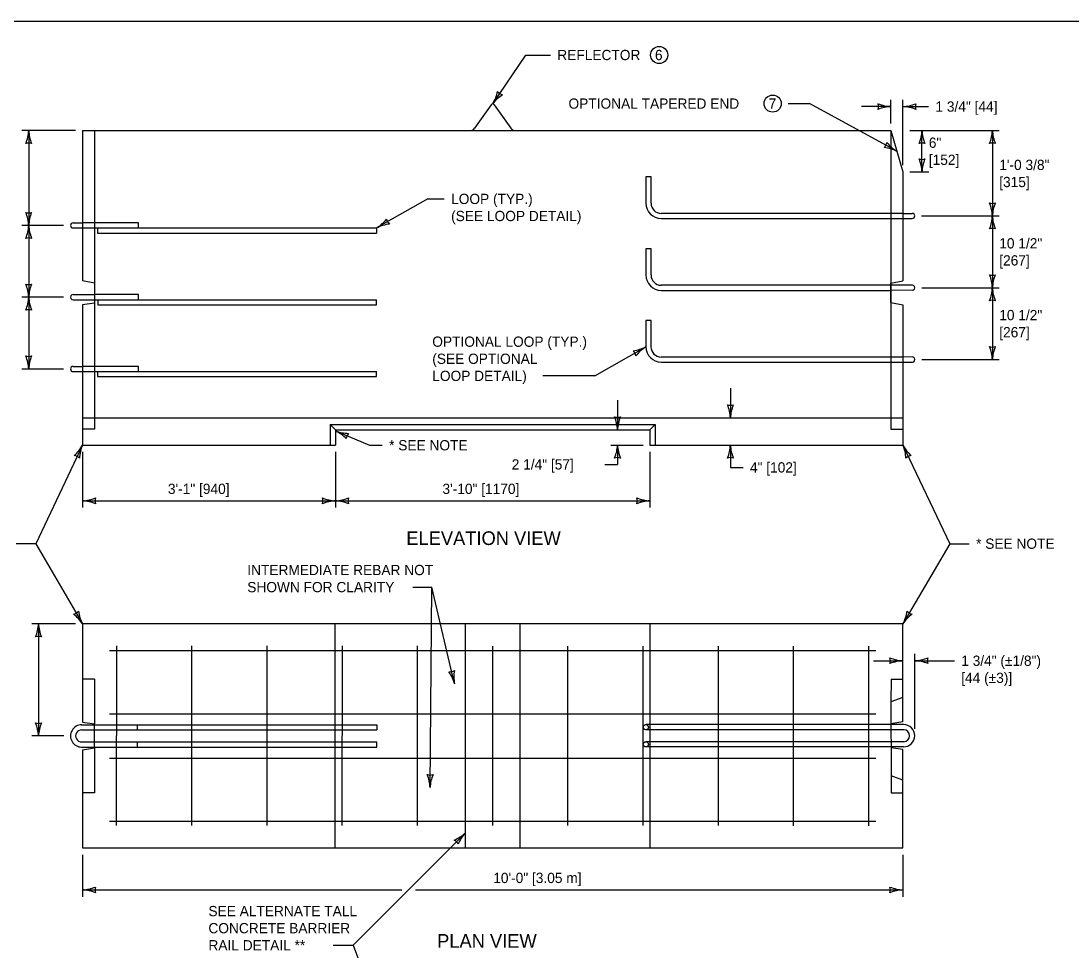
# Model space of a CAD drawing. Extents: x 49991.4 to 50021, y 49987.6 to 50011.4.
# Drawn here: x 50002.72 to 50008.86, y 49993.56 to 49999 of the extents above; entities that cross this region are included whole.
import ezdxf

# ---------------------------------------------------------------- set-up
doc = ezdxf.new("R2010")
doc.units = 0
for name, color, linetype in [('Level 1', 7, 'Continuous'), ('Level 2', 7, 'Continuous'), ('Level 3', 7, 'Continuous'), ('Level 4', 7, 'Continuous')]:
    doc.layers.add(name, color=color, linetype=linetype)

msp = doc.modelspace()

# ---------------------------------------------------------------- linework, layer by layer
at = {"layer": 'Level 1'}
for p, q in [((50003.0765, 49998.3587), (50007.8065, 49998.3587)), ((50003.0765, 49998.3587), (50003.0765, 49997.4789)), ((50007.8065, 49998.3587), (50007.8765, 49998.1161)), ((50007.8765, 49998.1161), (50007.8765, 49997.4792)), ((50007.8765, 49997.8737), (50007.931, 49997.8737)), ((50003.0215, 49997.8187), (50003.0766, 49997.8185)), ((50007.8765, 49997.8437), (50007.9311, 49997.8439)), ((50003.0215, 49997.7886), (50003.0765, 49997.7886)), ((50003.1468, 49997.4652), (50003.0765, 49997.4789)), ((50003.1468, 49997.4652), (50003.1468, 49997.3494)), ((50007.8065, 49997.4654), (50007.8765, 49997.4792)), ((50007.8065, 49997.3532), (50007.8065, 49997.4654)), ((50007.9315, 49997.4539), (50007.8065, 49997.4537)), ((50003.0215, 49997.3986), (50003.1468, 49997.3987)), ((50007.9315, 49997.4238), (50007.8065, 49997.4237)), ((50003.0215, 49997.3687), (50003.1468, 49997.3688)), ((50003.1468, 49997.3494), (50003.0766, 49997.3389)), ((50003.0766, 49997.3389), (50003.0766, 49996.5187)), ((50007.8065, 49997.3532), (50007.8765, 49997.3392)), ((50007.8765, 49997.3392), (50007.8765, 49996.5187)), ((50007.9317, 49997.0338), (50007.8765, 49997.0336)), ((50003.0215, 49996.9787), (50003.0766, 49996.9789)), ((50007.8765, 49997.0036), (50007.9316, 49997.0037)), ((50003.0215, 49996.9487), (50003.0766, 49996.949)), ((50004.5264, 49996.6386), (50004.5565, 49996.6086)), ((50004.5264, 49996.6386), (50006.4265, 49996.6386)), ((50004.5264, 49996.6386), (50004.5264, 49996.5187)), ((50004.5565, 49996.6086), (50004.5565, 49996.5187)), ((50004.5565, 49996.6086), (50006.3964, 49996.6086)), ((50006.4265, 49996.6386), (50006.3964, 49996.6086)), ((50006.3964, 49996.6086), (50006.3964, 49996.5187)), ((50006.4265, 49996.6386), (50006.4265, 49996.5187)), ((50003.0766, 49996.5187), (50004.5565, 49996.5187)), ((50006.3964, 49996.5187), (50007.8765, 49996.5187)), ((50007.8766, 49995.4723), (50003.0766, 49995.4723)), ((50003.0766, 49995.4723), (50003.0766, 49994.898)), ((50005.3166, 49994.1623), (50005.3166, 49995.4723)), ((50005.6366, 49994.1623), (50005.6366, 49995.4723)), ((50007.8766, 49994.8989), (50007.8766, 49995.4723)), ((50003.2341, 49995.3166), (50007.7186, 49995.3166)), ((50003.2766, 49994.2932), (50003.2768, 49995.3438)), ((50003.7166, 49994.2931), (50003.7168, 49995.3437)), ((50004.1566, 49994.293), (50004.1568, 49995.3436)), ((50004.5966, 49994.2929), (50004.5968, 49995.3435)), ((50005.0366, 49994.2928), (50005.0368, 49995.3434)), ((50005.4766, 49994.2927), (50005.4768, 49995.3433)), ((50005.9166, 49994.2926), (50005.9168, 49995.3432)), ((50006.3566, 49994.2925), (50006.3568, 49995.343)), ((50006.7966, 49994.2924), (50006.7968, 49995.3429)), ((50007.2366, 49994.2923), (50007.2368, 49995.3428)), ((50007.6766, 49994.2922), (50007.6768, 49995.3427)), ((50007.8766, 49995.0416), (50007.8063, 49995.0166)), ((50007.8063, 49995.0166), (50007.8067, 49994.583)), ((50003.2341, 49994.9473), (50007.7186, 49994.9473)), ((50003.0714, 49994.8827), (50003.1469, 49994.8824)), ((50003.0766, 49994.898), (50003.1469, 49994.8872)), ((50003.1469, 49994.7474), (50003.1469, 49994.8872)), ((50007.8766, 49994.8989), (50007.8064, 49994.888)), ((50007.8808, 49994.8836), (50007.8064, 49994.8834)), ((50003.0714, 49994.8524), (50003.1469, 49994.8524)), ((50007.8808, 49994.8534), (50007.8064, 49994.8533)), ((50003.0714, 49994.7824), (50003.1469, 49994.7822)), ((50003.0714, 49994.7522), (50003.1469, 49994.7521)), ((50003.0766, 49994.7363), (50003.1469, 49994.7474)), ((50007.8808, 49994.7834), (50007.8065, 49994.7831)), ((50007.8808, 49994.7531), (50007.8066, 49994.753)), ((50007.8766, 49994.7372), (50007.8066, 49994.7483)), ((50003.0766, 49994.7363), (50003.0766, 49994.1623)), ((50003.2341, 49994.688), (50007.7186, 49994.688)), ((50007.8766, 49994.1623), (50007.8766, 49994.7372)), ((50007.8766, 49994.558), (50007.8067, 49994.583)), ((50003.2341, 49994.3179), (50007.7186, 49994.3179)), ((50003.0766, 49994.1623), (50007.8766, 49994.1623))]:
    msp.add_line(p, q, dxfattribs=at)
msp.add_lwpolyline([(49999.3835, 49998.9992), (50016.7501, 49998.9992), (50016.7501, 49987.7988), (49999.3835, 49987.7988)], close=True, dxfattribs=at)
for centre, radius, start, end in [((50007.931, 49997.8588), 0.0149, 270.58084, 89.93308), ((50003.0215, 49997.8037), 0.015, 90.00376, 269.98914), ((50007.9315, 49997.4388), 0.015, 269.99727, 90.00272), ((50003.0212, 49997.3837), 0.015, 88.80732, 271.23347), ((50007.9319, 49997.0188), 0.015, 268.79877, 90.74505), ((50003.0215, 49996.9637), 0.015, 90.04087, 269.95913)]:
    msp.add_arc(centre, radius, start, end, dxfattribs=at)
for centre, major_axis, start_param, end_param in [((50003.0714, 49994.8174), (0, 0.0652), 0, 3.141593), ((50007.8808, 49994.8184), (0, 0.0652), 3.141593, 6.283185), ((50003.0714, 49994.8174), (0, 0.035), 0, 3.141593), ((50007.8808, 49994.8184), (0, 0.035), 3.141593, 6.283185)]:
    msp.add_ellipse(centre, major_axis=major_axis, ratio=0.991158, start_param=start_param, end_param=end_param, dxfattribs=at)
at = {"layer": 'Level 2'}
for centre in [(50006.4502, 49998.8003), (50007.1145, 49998.5161)]:
    msp.add_circle(centre, 0.05, dxfattribs=at)
at = {"layer": 'Level 3'}
for p, q in [((50005.4765, 49998.5143), (50005.6707, 49998.8003)), ((50005.6707, 49998.8003), (50005.8145, 49998.8003)), ((50005.4683, 49998.5095), (50005.3703, 49998.3715)), ((50005.4847, 49998.5095), (50005.5826, 49998.3715)), ((50007.2045, 49998.5161), (50007.3289, 49998.5161)), ((50007.8416, 49998.2373), (50007.3289, 49998.5161)), ((50007.8065, 49998.4987), (50007.6331, 49998.4987)), ((50007.8065, 49998.3987), (50007.8065, 49998.5387)), ((50007.8765, 49998.1561), (50007.8765, 49998.5387)), ((50007.8765, 49998.4987), (50008.0264, 49998.4987)), ((50003.0365, 49998.3587), (50002.7221, 49998.3587)), ((50002.7621, 49998.3587), (50002.7621, 49997.8036)), ((50007.9165, 49998.3587), (50008.4398, 49998.3587)), ((50007.9878, 49998.1161), (50007.9878, 49998.3587)), ((50008.3998, 49998.3587), (50008.3998, 49997.8588)), ((50007.9165, 49998.1161), (50008.0278, 49998.1161)), ((50005.0967, 49997.9586), (50004.7975, 49997.7886)), ((50005.0967, 49997.9586), (50005.1932, 49997.9586)), ((50007.9859, 49997.8588), (50008.4398, 49997.8588)), ((50008.3998, 49997.8588), (50008.3998, 49997.4388)), ((50002.9665, 49997.8036), (50002.7222, 49997.8036)), ((50002.7621, 49997.8036), (50002.7622, 49997.3836)), ((50002.9663, 49997.3836), (50002.7222, 49997.3836)), ((50002.7622, 49997.3836), (50002.7622, 49996.9636)), ((50007.9866, 49997.4388), (50008.4398, 49997.4388)), ((50008.3998, 49997.4388), (50008.3998, 49997.0188)), ((50006.0734, 49996.9235), (50006.3725, 49997.0935)), ((50007.9869, 49997.0188), (50008.4398, 49997.0188)), ((50002.9665, 49996.9636), (50002.7222, 49996.9636)), ((50006.0734, 49996.9235), (50005.7705, 49996.9235)), ((50006.867, 49996.8522), (50006.867, 49996.6787)), ((50006.2067, 49996.782), (50006.2067, 49996.6086)), ((50004.5565, 49996.6011), (50004.7561, 49996.5176)), ((50003.0766, 49996.5187), (50002.8033, 49995.9416)), ((50003.0766, 49996.4787), (50003.0766, 49996.1526)), ((50004.5565, 49996.4787), (50004.5565, 49996.1526)), ((50004.7561, 49996.5176), (50004.8305, 49996.5176)), ((50006.1667, 49996.5187), (50006.3564, 49996.5187)), ((50006.2067, 49996.5187), (50006.2067, 49996.4055)), ((50006.3964, 49996.4787), (50006.3964, 49996.1526)), ((50006.867, 49996.5187), (50006.867, 49996.3881)), ((50007.8765, 49996.5187), (50008.1499, 49995.9418)), ((50006.1324, 49996.4055), (50006.2067, 49996.4055)), ((50006.867, 49996.3881), (50006.9414, 49996.3881)), ((50003.0766, 49996.1926), (50004.5565, 49996.1926)), ((50004.5565, 49996.1926), (50006.3964, 49996.1926)), ((50002.8033, 49995.9416), (50002.6888, 49995.9416)), ((50002.8033, 49995.9416), (50003.0766, 49995.4723)), ((50008.1499, 49995.9418), (50007.8766, 49995.4723)), ((50008.1499, 49995.9418), (50008.2644, 49995.9418)), ((50005.0083, 49995.6878), (50005.1197, 49995.6878)), ((50005.1098, 49994.5151), (50005.1197, 49995.6878)), ((50005.2532, 49995.1226), (50005.1197, 49995.6878)), ((50003.0366, 49995.4723), (50002.7795, 49995.4723)), ((50002.8195, 49995.4723), (50002.8195, 49994.8174)), ((50007.9452, 49994.8584), (50007.9452, 49995.2972)), ((50007.7032, 49995.2572), (50007.8766, 49995.2572)), ((50007.9452, 49995.2572), (50008.1774, 49995.2572)), ((50002.9667, 49994.8174), (50002.7795, 49994.8174)), ((50004.6608, 49993.5928), (50005.3166, 49994.2502)), ((50003.0765, 49994.1223), (50003.0765, 49993.8767)), ((50007.8765, 49994.1223), (50007.8765, 49993.8767)), ((50003.0765, 49993.9167), (50004.9439, 49993.9167)), ((50005.0239, 49993.9167), (50007.8765, 49993.9167)), ((50004.5422, 49993.5928), (50004.6608, 49993.5928)), ((50004.6608, 49993.5928), (50005.3799, 49991.6271))]:
    msp.add_line(p, q, dxfattribs=at)
for centre, radius, start, end in [((50005.2775, 49998.6355), 0.233, 328.64825, 347.8981), ((50005.6551, 49998.3819), 0.2223, 123.27695, 143.46046), ((50005.5485, 49998.6203), 0.0548, 217.95976, 253.68212), ((50005.4765, 49998.5037), 0.0101, 35.34894, 144.65106), ((50007.8157, 49998.7208), 0.2223, 247.45601, 267.63952), ((50007.6783, 49998.4987), 0.0548, 342.13882, 17.86118), ((50007.818, 49998.266), 0.233, 92.82731, 112.07716), ((50007.865, 49998.7314), 0.233, 272.82731, 292.07716), ((50007.8673, 49998.2766), 0.2223, 67.45601, 87.63952), ((50008.0047, 49998.4987), 0.0548, 162.13882, 197.86118), ((50005.3456, 49998.389), 0.0303, 270, 324.65106), ((50005.6073, 49998.389), 0.0303, 215.34894, 270), ((50002.54, 49998.3679), 0.2223, 337.45803, 357.64153), ((50002.9948, 49998.3702), 0.233, 182.82933, 202.07918), ((50007.7657, 49998.3679), 0.2223, 337.45601, 357.63952), ((50008.2206, 49998.3702), 0.233, 182.82731, 202.07716), ((50008.1776, 49998.3679), 0.2223, 337.45759, 357.6411), ((50008.6325, 49998.3702), 0.233, 182.82889, 202.07874), ((50002.7621, 49998.2305), 0.0548, 72.14083, 107.86319), ((50007.7289, 49998.2985), 0.0548, 313.60126, 349.32362), ((50007.7405, 49998.0273), 0.233, 64.28976, 83.53961), ((50007.9557, 49998.428), 0.2223, 218.91846, 239.10196), ((50007.9878, 49998.2305), 0.0548, 72.13882, 107.86118), ((50008.3998, 49998.2305), 0.0548, 72.1404, 107.86276), ((50007.9878, 49998.2444), 0.0548, 252.13882, 287.86118), ((50007.7551, 49998.1047), 0.233, 2.82731, 22.07716), ((50008.21, 49998.107), 0.2223, 157.45601, 177.63952), ((50008.3998, 49997.987), 0.0548, 252.1404, 287.86276), ((50008.1671, 49997.8473), 0.233, 2.82889, 22.07874), ((50008.6219, 49997.8497), 0.2223, 157.45759, 177.6411), ((50002.7621, 49997.9319), 0.0548, 252.14083, 287.86319), ((50002.5294, 49997.7921), 0.233, 2.82932, 22.07917), ((50002.9843, 49997.7945), 0.2223, 157.45802, 177.64153), ((50004.6798, 49997.9772), 0.2223, 301.96607, 322.14958), ((50004.909, 49997.8519), 0.0548, 191.74441, 227.46677), ((50008.1777, 49997.868), 0.2223, 337.45759, 357.6411), ((50008.6325, 49997.8703), 0.233, 182.82889, 202.07874), ((50002.54, 49997.8128), 0.2223, 337.45803, 357.64153), ((50002.9949, 49997.8151), 0.233, 182.82933, 202.07918), ((50004.9025, 49997.5806), 0.233, 97.52843, 116.77828), ((50008.3998, 49997.7306), 0.0548, 72.1404, 107.86276), ((50002.7622, 49997.6754), 0.0548, 72.14083, 107.86319), ((50008.3998, 49997.567), 0.0548, 252.1404, 287.86276), ((50008.1671, 49997.4273), 0.233, 2.82889, 22.07874), ((50008.6219, 49997.4297), 0.2223, 157.45759, 177.6411), ((50002.7622, 49997.5119), 0.0548, 252.14083, 287.86319), ((50002.5294, 49997.3721), 0.233, 2.82932, 22.07917), ((50002.9843, 49997.3745), 0.2223, 157.45802, 177.64153), ((50002.54, 49997.3928), 0.2223, 337.45803, 357.64153), ((50002.9949, 49997.3951), 0.233, 182.82933, 202.07918), ((50008.1777, 49997.448), 0.2223, 337.45759, 357.6411), ((50008.6325, 49997.4503), 0.233, 182.82889, 202.07874), ((50008.3998, 49997.3106), 0.0548, 72.1404, 107.86276), ((50002.7622, 49997.2554), 0.0548, 72.14083, 107.86319), ((50006.2676, 49997.3015), 0.233, 277.52842, 296.77828), ((50006.4902, 49996.9049), 0.2223, 121.96607, 142.14957), ((50008.3998, 49997.147), 0.0548, 252.1404, 287.86276), ((50008.1671, 49997.0073), 0.233, 2.82889, 22.07874), ((50008.622, 49997.0097), 0.2223, 157.45759, 177.6411), ((50002.7622, 49997.0919), 0.0548, 252.14083, 287.86319), ((50002.5295, 49996.9521), 0.233, 2.82932, 22.07917), ((50002.9843, 49996.9545), 0.2223, 157.45802, 177.64153), ((50006.2611, 49997.0301), 0.0548, 11.74441, 47.46677), ((50006.867, 49996.8069), 0.0548, 252.13882, 287.86118), ((50006.6343, 49996.6672), 0.233, 2.82731, 22.07716), ((50007.0892, 49996.6696), 0.2223, 157.45601, 177.63952), ((50006.2067, 49996.7368), 0.0548, 252.13882, 287.86118), ((50005.974, 49996.5971), 0.233, 2.82731, 22.07716), ((50006.4289, 49996.5994), 0.2223, 157.45601, 177.63952), ((50004.4622, 49996.3998), 0.2223, 44.73985, 64.92336), ((50004.6357, 49996.8202), 0.233, 250.11115, 269.361), ((50004.6747, 49996.5516), 0.0548, 139.42266, 175.14502), ((50002.8797, 49996.622), 0.2223, 312.11968, 332.30319), ((50003.2918, 49996.4295), 0.233, 157.49098, 176.74083), ((50005.9846, 49996.5279), 0.2223, 337.45601, 357.63952), ((50006.4395, 49996.5302), 0.233, 182.82731, 202.07716), ((50006.6449, 49996.5279), 0.2223, 337.45601, 357.63952), ((50007.0998, 49996.5302), 0.233, 182.82731, 202.07716), ((50007.6718, 49996.4319), 0.2223, 2.80835, 22.99186), ((50008.0819, 49996.6287), 0.233, 208.17965, 227.4295), ((50003.0217, 49996.4028), 0.0548, 46.80249, 82.52485), ((50006.2067, 49996.3905), 0.0548, 72.13882, 107.86118), ((50006.867, 49996.3905), 0.0548, 72.13882, 107.86118), ((50007.9314, 49996.4028), 0.0548, 97.49116, 133.21352), ((50003.0651, 49996.4253), 0.233, 272.82731, 292.07716), ((50003.0674, 49995.9705), 0.2223, 67.45601, 87.63952), ((50003.2048, 49996.1926), 0.0548, 162.13882, 197.86118), ((50004.5656, 49996.4147), 0.2223, 247.45601, 267.63952), ((50004.4282, 49996.1926), 0.0548, 342.13882, 17.86118), ((50004.568, 49995.9599), 0.233, 92.82731, 112.07716), ((50004.545, 49996.4253), 0.233, 272.82731, 292.07716), ((50004.5473, 49995.9705), 0.2223, 67.45601, 87.63952), ((50004.6847, 49996.1926), 0.0548, 162.13882, 197.86118), ((50006.4056, 49996.4147), 0.2223, 247.45601, 267.63952), ((50006.2682, 49996.1926), 0.0548, 342.13882, 17.86118), ((50006.4079, 49995.9599), 0.233, 92.82731, 112.07716), ((50003.0121, 49995.5831), 0.0548, 282.34946, 318.07182), ((50003.2732, 49995.5762), 0.2223, 187.66665, 207.85016), ((50007.6697, 49995.5794), 0.233, 332.624, 351.87385), ((50007.9411, 49995.5831), 0.0548, 221.93551, 257.65787), ((50002.8813, 49995.3453), 0.233, 33.03795, 52.2878), ((50008.064, 49995.3526), 0.2223, 127.2527, 147.43621), ((50002.5973, 49995.4814), 0.2223, 337.45601, 357.63952), ((50003.0522, 49995.4838), 0.233, 182.82731, 202.07716), ((50002.8195, 49995.3441), 0.0548, 72.13882, 107.86118), ((50007.8858, 49995.4793), 0.2223, 247.45601, 267.63952), ((50007.7484, 49995.2572), 0.0548, 342.13882, 17.86118), ((50007.8881, 49995.0245), 0.233, 92.82731, 112.07716), ((50007.9337, 49995.4899), 0.233, 272.82731, 292.07716), ((50007.936, 49995.035), 0.2223, 67.45601, 87.63952), ((50008.0734, 49995.2572), 0.0548, 162.13882, 197.86118), ((50005.2237, 49995.2474), 0.0548, 265.42436, 301.14672), ((50005.0293, 49995.058), 0.233, 16.11285, 35.3627), ((50005.4715, 49995.1648), 0.2223, 170.74155, 190.92506), ((50002.8195, 49994.9457), 0.0548, 252.13882, 287.86118), ((50002.5867, 49994.8059), 0.233, 2.82731, 22.07716), ((50003.0416, 49994.8083), 0.2223, 157.45601, 177.63952), ((50005.1108, 49994.6433), 0.0548, 251.65224, 287.3746), ((50004.877, 49994.5056), 0.233, 2.34073, 21.59058), ((50005.3318, 49994.5041), 0.2223, 156.96943, 177.15294), ((50005.1658, 49994.4136), 0.2223, 292.52743, 312.71094), ((50005.4894, 49994.094), 0.233, 137.89873, 157.14858), ((50005.226, 49994.1594), 0.0548, 27.21024, 62.9326), ((50003.0651, 49994.1494), 0.233, 272.82731, 292.07716), ((50003.0674, 49993.6946), 0.2223, 67.45601, 87.63952), ((50003.2048, 49993.9167), 0.0548, 162.13882, 197.86118), ((50007.8857, 49994.1388), 0.2223, 247.45601, 267.63952), ((50007.7483, 49993.9167), 0.0548, 342.13882, 17.86118), ((50007.888, 49993.684), 0.233, 92.82731, 112.07716)]:
    msp.add_arc(centre, radius, start, end, dxfattribs=at)
at = {"layer": 'Level 4'}
for p, q in [((50003.1468, 49998.3587), (50003.1468, 49997.4652)), ((50007.8065, 49998.3587), (50007.8065, 49996.6123)), ((50006.4026, 49998.0867), (50006.3726, 49998.0867)), ((50006.3726, 49998.0867), (50006.3726, 49997.9335)), ((50006.4026, 49997.9335), (50006.4026, 49998.0867)), ((50007.8765, 49997.8737), (50006.4625, 49997.8737)), ((50003.4051, 49997.8185), (50003.0766, 49997.8185)), ((50003.4051, 49997.8185), (50003.0766, 49997.8185)), ((50003.4051, 49997.7886), (50003.4051, 49997.8185)), ((50006.4625, 49997.8437), (50007.8765, 49997.8437)), ((50003.0766, 49997.7886), (50004.7975, 49997.7886)), ((50003.1654, 49997.7886), (50003.1654, 49997.7586)), ((50003.1654, 49997.7586), (50004.7975, 49997.7586)), ((50004.7975, 49997.7886), (50004.7975, 49997.7586)), ((50006.4028, 49997.6667), (50006.3727, 49997.6667)), ((50006.3727, 49997.6667), (50006.3727, 49997.5135)), ((50006.4028, 49997.5135), (50006.4028, 49997.6667)), ((50007.8065, 49997.4537), (50006.4626, 49997.4537)), ((50003.4052, 49997.3987), (50003.1468, 49997.3987)), ((50003.4052, 49997.3688), (50003.4052, 49997.3987)), ((50006.4626, 49997.4237), (50007.8065, 49997.4237)), ((50003.1468, 49997.3688), (50004.7976, 49997.3688)), ((50003.1468, 49997.3494), (50003.1468, 49996.6123)), ((50003.1655, 49997.3688), (50003.1655, 49997.3388)), ((50003.1655, 49997.3388), (50004.7976, 49997.3388)), ((50004.7976, 49997.3388), (50004.7976, 49997.3688)), ((50006.4026, 49997.2466), (50006.3725, 49997.2466)), ((50006.3725, 49997.2466), (50006.3725, 49997.0935)), ((50006.4026, 49997.0935), (50006.4026, 49997.2466)), ((50007.8765, 49997.0336), (50006.4624, 49997.0336)), ((50003.4051, 49996.9789), (50003.0766, 49996.9789)), ((50003.4051, 49996.949), (50003.4051, 49996.9789)), ((50006.4624, 49997.0036), (50007.8765, 49997.0036)), ((50003.0766, 49996.949), (50004.7975, 49996.949)), ((50003.1654, 49996.949), (50003.1654, 49996.9191)), ((50003.1654, 49996.9191), (50004.7975, 49996.9191)), ((50004.7975, 49996.9191), (50004.7975, 49996.949)), ((50003.0766, 49996.6787), (50007.8765, 49996.6787)), ((50003.1468, 49996.6123), (50003.0766, 49996.6123)), ((50007.8065, 49996.6123), (50007.8765, 49996.6123)), ((50004.5557, 49994.1623), (50004.5557, 49995.4723)), ((50006.3972, 49994.1623), (50006.3972, 49995.4723)), ((50003.1469, 49995.1501), (50003.0766, 49995.1501)), ((50003.1469, 49995.1501), (50003.1469, 49994.8872)), ((50007.8067, 49995.1501), (50007.8063, 49995.0166)), ((50007.8067, 49995.1501), (50007.8766, 49995.1501)), ((50003.1469, 49994.8824), (50004.7979, 49994.8824)), ((50003.3991, 49994.8524), (50003.3991, 49994.8824)), ((50004.7979, 49994.8824), (50004.7979, 49994.8524)), ((50007.8064, 49994.8834), (50006.3725, 49994.8834)), ((50003.1469, 49994.8524), (50004.7979, 49994.8524)), ((50007.8064, 49994.8533), (50006.3725, 49994.8533)), ((50003.1469, 49994.7822), (50004.7979, 49994.7822)), ((50003.1469, 49994.7521), (50004.7979, 49994.7521)), ((50003.1469, 49994.7474), (50003.1469, 49994.4845)), ((50003.3991, 49994.7521), (50003.3991, 49994.7822)), ((50004.7979, 49994.7521), (50004.7979, 49994.7822)), ((50007.8065, 49994.7831), (50006.3725, 49994.7831)), ((50007.8066, 49994.753), (50006.3725, 49994.753)), ((50007.8067, 49994.583), (50007.8067, 49994.4845)), ((50003.1469, 49994.4845), (50003.0766, 49994.4845)), ((50007.8067, 49994.4845), (50007.8766, 49994.4845)), ((50004.5422, 49993.5928), (50004.5422, 49993.5928))]:
    msp.add_line(p, q, dxfattribs=at)
for centre in [(50006.3725, 49994.8683), (50006.3725, 49994.7681)]:
    msp.add_circle(centre, 0.015, dxfattribs=at)
for centre, radius, start, end in [((50006.4631, 49997.9342), 0.0905, 180.43427, 269.60389), ((50006.4625, 49997.9335), 0.0599, 180, 270), ((50006.4632, 49997.5142), 0.0905, 180.43427, 269.60389), ((50006.4626, 49997.5135), 0.0599, 180, 270), ((50006.4631, 49997.0942), 0.0905, 180.43427, 269.60389), ((50006.4624, 49997.0935), 0.0599, 180, 270)]:
    msp.add_arc(centre, radius, start, end, dxfattribs=at)

# ---------------------------------------------------------------- texts
at = {"layer": 'Level 2'}
for s, height, p in [('REFLECTOR', 0.06, (50005.8545, 49998.7703)), ('6', 0.06, (50006.4257, 49998.7703)), ('OPTIONAL TAPERED END', 0.06, (50005.9199, 49998.4861)), ('7', 0.06, (50007.0907, 49998.4861)), ('1 3/4" [44]', 0.06, (50008.0664, 49998.4687)), ('6"', 0.06, (50008.0278, 49998.2574)), ('[152]', 0.06, (50008.0278, 49998.1574)), ('1\'-0 3/8"', 0.06, (50008.4398, 49998.1275)), ('[315]', 0.06, (50008.4398, 49998.0275)), ('LOOP (TYP.)', 0.06, (50005.2332, 49997.9286)), ('(SEE LOOP DETAIL)', 0.06, (50005.2332, 49997.8286)), ('10 1/2"', 0.06, (50008.4398, 49997.6689)), ('[267]', 0.06, (50008.4398, 49997.5689)), ('10 1/2"', 0.06, (50008.4398, 49997.2489)), ('[267]', 0.06, (50008.4398, 49997.1489)), ('OPTIONAL LOOP (TYP.)', 0.06, (50005.1229, 49997.0935)), ('(SEE OPTIONAL', 0.06, (50005.1229, 49996.9935)), ('LOOP DETAIL)', 0.06, (50005.1229, 49996.8935)), ('* SEE NOTE', 0.06, (50004.8705, 49996.4876)), ('2 1/4" [57]', 0.06, (50005.5878, 49996.3755)), ('4" [102]', 0.06, (50006.9814, 49996.3581)), ('3\'-1" [940]', 0.06, (50003.5764, 49996.2326)), ('3\'-10" [1170]', 0.06, (50005.1825, 49996.2326)), ('ELEVATION VIEW', 0.08, (50004.9711, 49995.9341)), ('* SEE NOTE', 0.06, (50008.3044, 49995.9118)), ('INTERMEDIATE REBAR NOT', 0.06, (50004.0406, 49995.7578)), ('SHOWN FOR CLARITY', 0.06, (50004.0406, 49995.6578)), ('1 3/4" (±1/8")', 0.06, (50008.2174, 49995.2272)), ('[44 (±3)]', 0.06, (50008.2174, 49995.1272)), ('10\'-0" [3.05 m]', 0.06, (50005.4796, 49993.9567)), ('SEE ALTERNATE TALL', 0.06, (50003.8134, 49993.7628)), ('CONCRETE BARRIER ', 0.06, (50003.8134, 49993.6628)), ('PLAN VIEW', 0.08, (50005.1513, 49993.5782)), ('RAIL DETAIL **', 0.06, (50003.8134, 49993.5628))]:
    msp.add_text(s, height=height, dxfattribs=at).set_placement(p)

doc.saveas('drawing.dxf')
